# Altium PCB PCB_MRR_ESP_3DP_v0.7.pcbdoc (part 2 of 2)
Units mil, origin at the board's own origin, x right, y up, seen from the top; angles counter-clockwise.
Board outline 5220 x 5030 mil, 2 copper layers (Top Layer, Bottom Layer); 131 components, 154 nets, 480 pads, 88 vias.
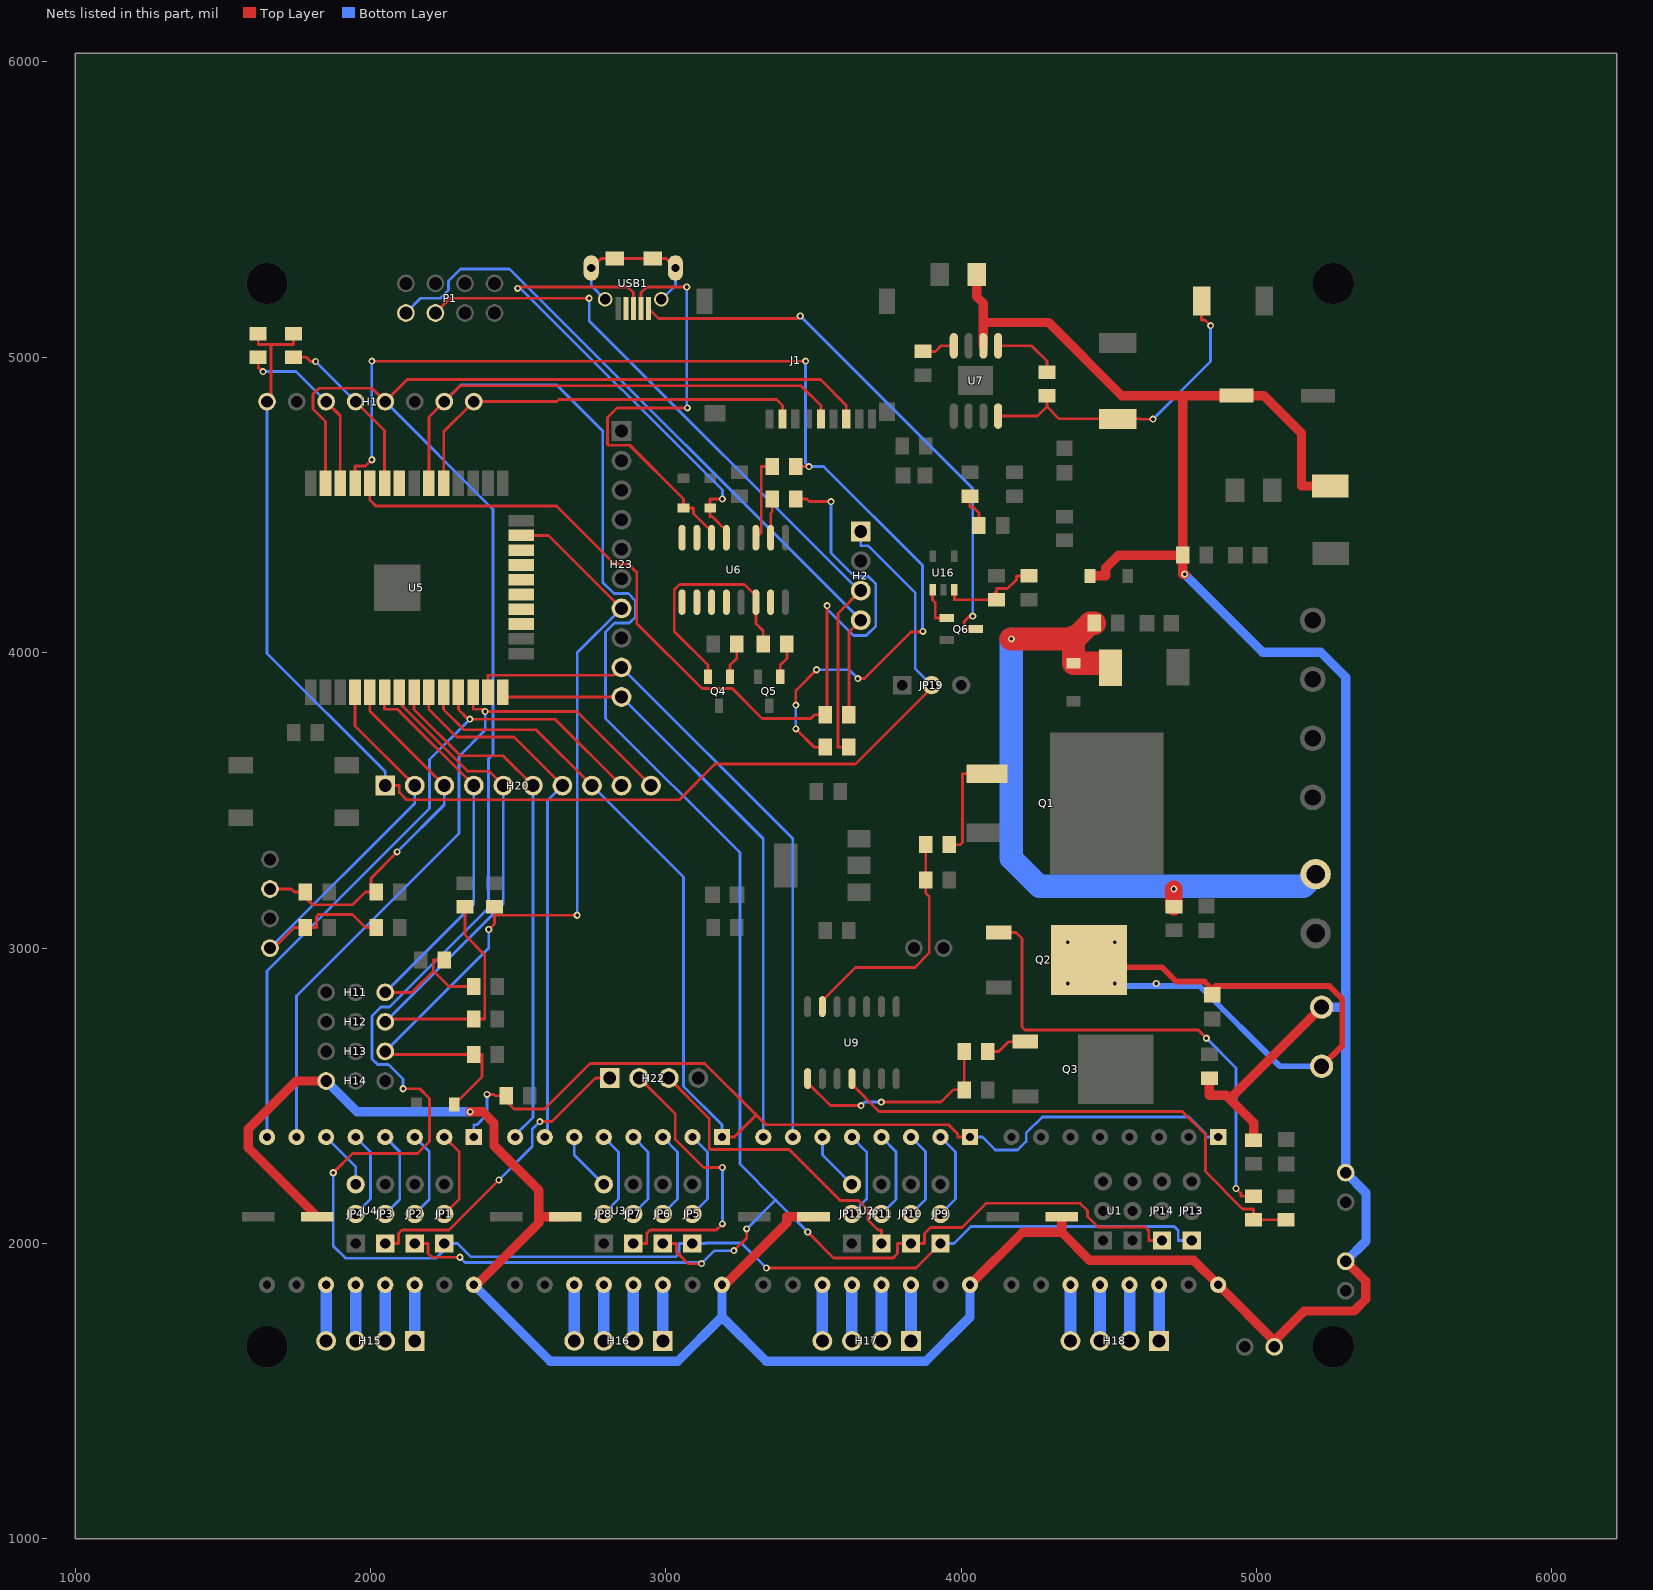
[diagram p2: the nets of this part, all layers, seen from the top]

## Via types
v1: diameter 24.02, hole 12.2, Top Layer to Bottom Layer, 71 vias
v2: diameter 24.4, hole 12, Top Layer to Bottom Layer, 17 vias

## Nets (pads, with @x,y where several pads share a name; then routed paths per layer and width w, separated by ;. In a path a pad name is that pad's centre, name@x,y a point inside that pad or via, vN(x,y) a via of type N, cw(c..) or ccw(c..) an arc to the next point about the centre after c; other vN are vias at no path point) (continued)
MOSI: H1.5 J1.7 JP1.1 JP5.1 JP9.1 JP13.1 U5.37 | length 9016.5
  Top Layer w9.45: U5.37@1848.1,4574.1 1848.1,4782.8 1805.7,4825.2 1805.7,4875.2 1825.5,4895 2005,4895 H1.5@2050,4850 2124.5,4924.5 3523.3,4924.5 3611,4836.8 J1.7@3611,4791 ; v1(1874.2,2239.4) 1939.6,2304.9 2160,2304.9 2200,2344.9 2200,2490.4 2166.8,2523.6 v1(2110.7,2523.6) ; v1(3340.5,1916.9) 3846.9,1916.9 JP9.1@3930,2000
  Bottom Layer w9.45: v1(1874.2,2239.4) 1874.2,1991.2 1915.1,1950.2 2222.9,1950.2 JP1.1@2272.6,2000 ; H1.5@2050,4850 2414.8,4485.2 2414.8,3655.4 2400,3640.6 2400,3135.3 2064.7,2800 2035.2,2800 2005.7,2770.5 2005.7,2624.8 2024.8,2605.7 2061.4,2605.7 2110.7,2556.5 v1(2110.7,2523.6) ; JP1.1@2250,2000 JP1.1@2272.6,2000 ; v1(3340.5,1916.9) 3255.5,2001.9 3137.1,2001.9 3135.3,2000 JP5.1@3090,2000 3044.7,2000 3044.7,1966 3033.4,1954.7 2340.5,1954.7 2295.3,2000 JP1.1@2272.6,2000 ; JP9.1@3930,2000 3975.3,2000 4032.6,2057.3 4721.4,2057.3 4734.7,2043.9 4734.7,2010 JP13.1@4780,2010
MOTOR_EN_PIN: H20.8 R26.1 U1.1 U2.1 U3.1 U4.1 U5.10 | length 5157.6
  Top Layer w9.45: U5.10@2247.8,3865.8 2247.8,3808.2 2317.1,3739 2561,3739 H20.8@2750,3550 ; v1(2394.7,2504.6) 2418.4,2504.6 2422.9,2500 R26.1@2441.5,2500 ; R26.1@2460,2500 R26.1@2441.5,2500 ; U3.1@3190,2360 3231.8,2360 3306.1,2434.3 ; U2.1@4030,2360 3988.2,2360 3988.2,2370.4 3956.9,2401.8 3338.7,2401.8 3306.1,2434.3 ; R26.1@2441.5,2500 2486.2,2455.2 2589.5,2455.2 2743.1,2608.8 3131.6,2608.8 3306.1,2434.3
  Bottom Layer w9.45: U4.1@2350,2360 2350,2401.8 2360.4,2401.8 2394.7,2436 v1(2394.7,2504.6) ; H20.8@2750,3550 3060,3240 3060,2531.8 3190,2401.8 U3.1@3190,2360 ; U2.1@4030,2360 4071.8,2360 4115.6,2316.2 4190.7,2316.2 4220,2345.5 4220,2373.6 4274.7,2428.3 4770.3,2428.3 4828.2,2370.4 4828.2,2360 U1.1@4870,2360
Q2_1: Q2.1 R7.2 | length 1652.7
  Top Layer w9.45: Q2.1@4127.4,3053 4185,3053 4205.5,3032.4 4205.5,2733.2 4216.3,2722.4 4802.4,2722.4 v1(4830,2694.7) ; v1(4930.4,2186.1) 4946.8,2169.7 4946.8,2159.9 R7.2@4990,2159.9
  Bottom Layer w9.45: v1(4830,2694.7) 4930.4,2594.3 v1(4930.4,2186.1)
Q2_4: LED6.2 P7.1 Q2.4 | length 2134
  Top Layer w19.68: Q2.4@4432.7,2960 4432.7,2942.3 4440,2935 4679.6,2935 4727.9,2886.7 4823.3,2886.7 LED6.2@4850.1,2859.9 ; LED6.2@4850.1,2842 LED6.2@4850.1,2859.9 ; P7.1@5220,2600 5289.7,2669.7 5289.7,2827.9 5245.9,2871.6 4861.7,2871.6 LED6.2@4850.1,2859.9
  Bottom Layer w19.68: 4437.5,2950 4515.8,2871.7 4806.7,2871.7 5078.3,2600 P7.1@5220,2600
  other v2: 4360,2880 4520,2880 4660,2880 4360,3020 4520,3020
Q4_1: Q4.1 R19.2 | length 120.2
  Top Layer w9.45: Q4.1@3217.4,3919.2 3217.4,3958.1 3240,3980.7 R19.2@3240,4030
Q5_1: Q5.1 R18.2 | length 120.2
  Top Layer w9.45: Q5.1@3387.4,3919.2 3387.4,3958.1 3410,3980.7 R18.2@3410,4030
R5_2: Q1.1 R5.2 | length 363.3
  Top Layer w9.45: R5.2@3960,3350 3997.1,3350 4004.3,3357.3 4004.3,3590 Q1.1@4087.5,3590
R9_2: Q3.1 R9.2 | length 141.2
  Top Layer w9.45: R9.2@4089.95,2650 4127.1,2650 4127.1,2650.2 4159.8,2683 Q3.1@4217.4,2683
R31_1: C9.1 R31.1 | length 118.5
  Top Layer w9.45: R31.1@4030,4530 4030,4492.9 4040.3,4492.9 4060,4473.2 C9.1@4060,4430
RTS: Q4.2 R18.1 U6.14 | length 814
  Top Layer w9.45: Q4.2@3142.6,3919.2 3142.6,3958.1 3028.3,4072.4 3028.3,4212.9 3046.2,4230.9 3266.6,4230.9 3305,4192.4 U6.14@3305,4171 3305,4098.2 3330,4073.2 R18.1@3330,4030
RX: R17.2 R28.1 U5.34 | length 3251.7
  Top Layer w9.45: U5.34@1998,4574 1998,4516.4 2018.1,4496.4 2630.5,4496.4 2826.9,4300 2873.6,4300 2901.6,4272 2901.6,4099.3 3122.2,3878.7 3224.9,3878.7 3326,3777.6 3490.5,3777.6 3502.9,3790 R28.1@3521.5,3790 ; R17.2@3440,4520 3477.1,4520 3485.7,4511.3 v1(3559.1,4511.3) ; R28.1@3540,3790 R28.1@3521.5,3790 ; v1(3546,4159.1) 3546,3814.5 R28.1@3521.5,3790
  Bottom Layer w9.45: v1(3546,4159.1) 3546,4147.7 3635.7,4057.9 3678.5,4057.9 3711,4090.4 3711,4231.9 3685.2,4257.7 3639.2,4257.7 3559.1,4337.8 v1(3559.1,4511.3)
RXD: H2.4 P1.8 R28.2 | length 2448.7
  Top Layer w9.45: R28.2@3620,3790 3620,4070 H2.4@3660,4110
  Bottom Layer w9.45: P1.8@2120,5150 2170,5200 2236.9,5200 2264.3,5227.4 2264.3,5257.9 2305.3,5299 2471,5299 H2.4@3660,4110
S$12: 
S$15: 
S$17: 
S$18: 
S$20: 
S$26: 
S$28: 
S$39: 
S$41: 
S$43: 
S$91: 
S$93: 
S$150: 
S$152: 
S$180: 
S$236: 
S$240: 
SCK: H1.7 J1.5 JP2.1 JP6.1 JP10.1 JP14.1 U5.30 | length 8421.4
  Top Layer w9.45: JP2.1@2150,2000 2195.3,2000 2195.3,1966 2208,1953.3 v1(2302.6,1953.3) ; U5.30@2197.9,4573.9 2197.9,4797.9 H1.7@2250,4850 2303.8,4903.8 3457.9,4903.8 3525,4836.8 J1.5@3525,4791 ; JP6.1@2990,2000 3035.3,2000 3035.3,1971.8 3075.6,1931.5 v1(3120.7,1931.5) ; v1(3230.5,1975.6) 3273.8,2018.9 v1(3273.8,2049.4) ; v1(3480.5,2038.9) 3568.3,1951.1 3769.8,1951.1 3784.7,1966.1 3784.7,2000 JP10.1@3830,2000 3852.6,2000 3875.3,2000 3875.3,2033.5 3895.9,2054.2 4002.5,2054.2 4084,2135.8 4402.4,2135.8 4427.2,2111 4427.2,2091.7 4463.6,2055.3 4623.4,2055.3 4634.7,2043.9 4634.7,2010 JP14.1@4680,2010
  Bottom Layer w9.45: H1.7@2250,4850 2306.2,4906.2 2630.6,4906.2 2786.5,4750.3 2786.5,4238.2 2824.7,4200 2873.1,4200 2897.7,4175.4 2897.7,4121.3 2876.4,4100 2826.9,4100 2796.3,4069.4 2796.3,3777.8 3250.8,3323.3 3250.8,2268.6 3371.9,2147.5 ; v1(2302.6,1953.3) 2320.1,1935.7 3116.5,1935.7 v1(3120.7,1931.5) 3164.9,1975.6 v1(3230.5,1975.6) ; v1(3273.8,2049.4) 3371.9,2147.5 ; v1(3480.5,2038.9) 3371.9,2147.5
SCL: H1.3 R20.1 U5.36 | length 609.7
  Top Layer w9.45: R20.1@1620,5000 1620,4962.9 1625,4962.9 v1(1636.4,4951.6) ; H1.3@1850,4850 1898,4802 U5.36@1898,4574
  Bottom Layer w9.45: v1(1636.4,4951.6) 1748.4,4951.6 H1.3@1850,4850
SDA: H1.4 R21.1 U5.33 | length 588.7
  Top Layer w9.45: R21.1@1740,5000 1783.2,5000 1797.6,4985.6 v1(1814.4,4985.6) ; H1.4@1950,4850 2048,4752 U5.33@2048,4574
  Bottom Layer w9.45: v1(1814.4,4985.6) H1.4@1950,4850
SS: H1.8 J1.2 U5.29 | length 1420.2
  Top Layer w9.45: U5.29@2247.9,4573.9 2247.9,4747.9 H1.8@2350,4850 2631.1,4850 2637.8,4856.7 3375,4856.7 3395,4836.8 J1.2@3395,4791
TEMP_BED_PIN: C6.1 H10.1 H20.3 R12.1 U5.5 | length 1301.7
  Top Layer w9.45: H10.1@1660,3200 1732.9,3200 1742.9,3190 C6.1@1761.5,3190 ; C6.1@1780,3190 C6.1@1761.5,3190 ; U5.5@1997.9,3865.9 1997.9,3802.1 H20.3@2250,3550 ; R12.1@2020,3190 R12.1@2001.5,3190 ; v1(2090.4,3325.5) 2001.5,3236.5 R12.1@2001.5,3190 ; C6.1@1761.5,3190 1804.6,3146.8 1939.8,3146.8 1982.9,3190 R12.1@2001.5,3190
  Bottom Layer w9.45: v1(2090.4,3325.5) 2250,3485.1 H20.3@2250,3550
TEMP_E0_PIN: C5.1 H9.1 H20.2 R11.1 U5.4 | length 1599.1
  Top Layer w9.45: H9.1@1660,3000 1672.9,3000 1742.9,3070 C5.1@1780,3070 1817.1,3070 1817.1,3107.1 1823.2,3113.2 1939.8,3113.2 1982.9,3070 R11.1@2020,3070 ; U5.4@1947.9,3865.9 1947.9,3752.1 H20.2@2150,3550
  Bottom Layer w9.45: H9.1@1660,3000 2150,3490 H20.2@2150,3550
TO_E0: R7.1 R8.1 U9.11 | length 1774.3
  Top Layer w9.45: U9.11@3630,2558 3630,2538.8 3722.1,2446.8 4748.2,2446.8 4826.7,2368.2 4826.7,2243.2 4952.9,2117.1 4990,2117.1 4990,2079.9 R8.1@5100,2079.9
TO_FAN_E0: R9.1 R10.1 U9.8 | length 727.9
  Top Layer w9.45: U9.8@3480,2558 3480,2544.2 3557.5,2466.7 v1(3661.1,2466.7) ; v1(3729.2,2478.6) 3931.4,2478.6 3972.8,2520 R10.1@4009.95,2520 R9.1@4009.95,2650
  Bottom Layer w9.45: v1(3661.1,2466.7) 3673.1,2478.6 v1(3729.2,2478.6)
TO_HEAT_BED: R5.1 R6.1 U9.6 | length 820.5
  Top Layer w9.45: U9.6@3530,2802 3530,2822.7 3641.8,2934.5 3843.1,2934.5 3891.6,2983.1 3891.6,3175.2 3880,3186.8 R6.1@3880,3230 R5.1@3880,3350
TX: R16.2 R27.1 U5.35 | length 3871.8
  Top Layer w9.45: U5.35@1948,4574 1948,4631.6 1983.2,4631.6 v1(2004.8,4653.2) ; v1(2004.8,4986.9) v1(3473.3,4986.9) ; R16.2@3440,4630 v1(3484.9,4630) ; v1(3440.2,3742.2) 3502.4,3680 R27.1@3540,3680 ; v1(3440.2,3822.2) 3440.2,3872.2 v1(3510.2,3942.2) ; v1(3650.2,3912.2) 3672.2,3912.2 3830,4070 3868,4070 v1(3870.2,4072.2)
  Bottom Layer w9.45: v1(2004.8,4653.2) v1(2004.8,4986.9) ; v1(3440.2,3742.2) v1(3440.2,3822.2) ; v1(3473.3,4986.9) 3473.3,4641.6 v1(3484.9,4630) 3534.4,4630 3868.5,4295.9 3868.5,4073.9 v1(3870.2,4072.2) ; v1(3510.2,3942.2) 3620.2,3942.2 v1(3650.2,3912.2)
TXD: H2.3 P1.6 R27.2 | length 2514.5
  Top Layer w9.45: P1.6@2220,5150 2270,5200 v1(2740.6,5200) ; R27.2@3620,3680 3582.9,3680 3582.9,4132.9 H2.3@3660,4210
  Bottom Layer w9.45: v1(2740.6,5200) 2740.6,5123.7 3654.2,4210 H2.3@3660,4210
U1_11: H18.4 U1.11 | length 190
  Bottom Layer w39.37: H18.4@4370,1670 U1.11@4370,1860
U1_12: H18.3 U1.12 | length 190
  Bottom Layer w39.37: H18.3@4470,1670 U1.12@4470,1860
U1_13: H18.2 U1.13 | length 190
  Bottom Layer w39.37: H18.2@4570,1670 U1.13@4570,1860
U1_14: H18.1 U1.14 | length 190
  Bottom Layer w39.37: H18.1@4670,1670 U1.14@4670,1860
U2_11: H17.4 U2.11 | length 190
  Bottom Layer w39.37: H17.4@3530,1670 U2.11@3530,1860
U2_12: H17.3 U2.12 | length 190
  Bottom Layer w39.37: H17.3@3630,1670 U2.12@3630,1860
U2_13: H17.2 U2.13 | length 190
  Bottom Layer w39.37: H17.2@3730,1670 U2.13@3730,1860
U2_14: H17.1 U2.14 | length 190
  Bottom Layer w39.37: H17.1@3830,1670 U2.14@3830,1860
U3_11: H16.4 U3.11 | length 190
  Bottom Layer w39.37: H16.4@2690,1670 U3.11@2690,1860
U3_12: H16.3 U3.12 | length 190
  Bottom Layer w39.37: H16.3@2790,1670 U3.12@2790,1860
U3_13: H16.2 U3.13 | length 190
  Bottom Layer w39.37: H16.2@2890,1670 U3.13@2890,1860
U3_14: H16.1 U3.14 | length 190
  Bottom Layer w39.37: H16.1@2990,1670 U3.14@2990,1860
U4_11: H15.4 U4.11 | length 190
  Bottom Layer w39.37: H15.4@1850,1670 U4.11@1850,1860
U4_12: H15.3 U4.12 | length 190
  Bottom Layer w39.37: H15.3@1950,1670 U4.12@1950,1860
U4_13: H15.2 U4.13 | length 190
  Bottom Layer w39.37: H15.2@2050,1670 U4.13@2050,1860
U4_14: H15.1 U4.14 | length 190
  Bottom Layer w39.37: H15.1@2150,1670 U4.14@2150,1860
U5_17: U5.17
U5_18: U5.18
U5_19: U5.19
U5_20: U5.20
U5_21: U5.21
U5_22: U5.22
U5_32: U5.32
U6_2: R17.1 U6.2 | length 133.1
  Top Layer w9.45: U6.2@3355,4389 3355,4471.8 3360,4476.8 R17.1@3360,4520
U6_3: R16.1 U6.3 | length 285.5
  Top Layer w9.45: U6.3@3305,4389 3322.9,4406.9 3322.9,4630 R16.1@3360,4630
U6_5: D5.1 U6.5 USB1.3 | length 1662.8
  Top Layer w9.45: v1(2498.2,5233.5) 2503,5238.3 2870.9,5238.3 2890.5,5218.8 USB1.3@2890.5,5165.1 ; v1(3191.7,4520.1) 3150,4520.1 D5.1@3150,4490.05 3150,4460 3157.5,4460 3205,4412.5 U6.5@3205,4389
  Bottom Layer w9.45: v1(2498.2,5233.5) 2508.7,5233.5 3191.7,4550.5 v1(3191.7,4520.1)
U6_6: D6.1 U6.6 USB1.2 | length 1526.7
  Top Layer w9.45: USB1.2@2916,5165.1 2916,5218.8 2935.4,5238.1 v1(3070.9,5238.1) ; v1(3072.9,4828.5) 2835,4828.5 2802.2,4795.7 2802.2,4705 2805,4702.2 2877.8,4702.2 3060,4520.1 D6.1@3060,4490.05 3094,4490 3094,4471.1 3155,4410 U6.6@3155,4389
  Bottom Layer w9.45: v1(3070.9,5238.1) 3070.9,4830.5 v1(3072.9,4828.5)
U6_7: U6.7
U6_8: U6.8
U6_9: U6.9
U6_10: U6.10
U6_11: U6.11
U6_12: U6.12
U6_15: U6.15
U7_1: C15.1 U7.1 | length 223.6
  Top Layer w9.45: U7.1@4125,5039 4238.1,5039 4290,4987.1 C15.1@4290,4950
U7_4: R32.1 U7.4 | length 112.9
  Top Layer w9.45: R32.1@3870,5020 3913.2,5020 3932.2,5039 U7.4@3975,5039
U7_8: C15.2 D4.2 L1.1 U7.8 | length 1091.9
  Top Layer w9.45: U7.8@4125,4801 4258.1,4801 4290,4832.9 ; C15.2@4290,4870 4290,4832.9 ; v1(4649.4,4790.4) 4608.5,4790.4 4607.3,4791.6 D4.2@4530,4791.6 4331.3,4791.6 4290,4832.9 ; L1.1@4813.7,5190 4813.7,5126.5 4825.2,5126.5 v1(4844.2,5107.4)
  Bottom Layer w9.45: v1(4649.4,4790.4) 4844.2,4985.3 v1(4844.2,5107.4)
U16_1: Q6.1 U16.1 | length 138.1
  Top Layer w9.45: U16.1@3903.1,4213 3903.1,4179 3911.9,4170.1 3911.9,4117.4 Q6.1@3950.8,4117.4
U16_3: R23.1 R30.1 U16.3 | length 361.9
  Top Layer w9.45: U16.3@3977.1,4213 3977.1,4179 4090,4179 4120,4209 ; R23.1@4120,4179.99 4120,4208.3 4120,4209 ; R30.1@4230.01,4260 4186.8,4260 4186.8,4246.8 4157.1,4217.1 4120,4217.1 4120,4209
USB1_0: USB1.0 | length 564.6
  Top Layer w9.45: USB1.0@2747.5,5302.31 2748.8,5302.3 2781.4,5334.9 USB1.0@2827.2,5334.9 2873,5334.9 2873.6,5334.2 USB1.0@2956.3,5334.25 2979.2,5334.2 3002.1,5334.2 3002.1,5332.7 USB1.0@3032.5,5302.31
  Bottom Layer w9.45: USB1.0@2747.5,5302.31 2747.5,5242.8 USB1.0@2794.3,5196.01 ; USB1.0@2984.9,5196.01 3032.5,5243.6 USB1.0@3032.5,5302.31
USB1_4: USB1.4
VBED: CN2.2 D2.2 F1.2 R3.1 R14.1 | length 2409.1
  Top Layer w59.05: R3.1@4720,3140 v2(4720,3200)
  Top Layer w78.74: v1(4169.8,4046.5) 4380,4046.5 ; R14.1@4450,4100 4436.3,4100 4389.1,4052.8 4380,4052.8 4380,4046.5 ; F1.2@4505.7,3949.5 4491.2,3964 D2.2@4380,3964 4380,4046.5
  Bottom Layer w78.74: v1(4169.8,4046.5) 4169.8,3304.2 4264.8,3209.1 5159.1,3209.1 CN2.2@5200,3250
VIN: C1.1 C2.1 C3.1 C4.1 C8.1 C14.1 D1.2 F2.2 H7.1 H8.1 H14.1 H19.1 P7.2 R1.1 R2.1 R13.1 U1.16 U2.16 U3.16 U4.16 U7.2 | length 12891.1
  Top Layer w31.5: C1.1@1820,2090 1586.1,2323.9 1586.1,2387.6 1748.5,2550 H14.1@1850,2550 ; v1(2337.4,2445.4) 2380.5,2445.4 2418.4,2407.4 2418.4,2331.6 2569.4,2180.6 2569.4,2090 ; U4.16@2350,1860 2360.2,1860 2569.4,2069.3 2569.4,2090 ; C2.1@2660,2090 2569.4,2090 ; U3.16@3190,1860 3200.2,1860 3409.4,2069.3 3409.4,2090 C3.1@3500,2090 ; U2.16@4030,1860 4207.9,2037.8 4340,2037.8 ; C8.1@4052.99,5280 4053,5205.2 4075,5183.2 4075,5117.8 ; U7.2@4075,5039 4075,5117.8 ; C4.1@4340,2090 4340,2037.8 ; D1.2@4436,4260 4489.4,4260 4489.4,4286.7 4532.7,4330 R13.1@4750,4330 ; v1(4756.5,4265.6) 4750,4265.6 R13.1@4750,4330 ; R1.1@4840,2560 4840,2501.7 4896.6,2501.7 4909.2,2489.1 ; R2.1@4990.1,2350 4990.1,2408.3 4909.2,2489.1 ; H8.1@5060,1650 H8.1@5060,1670 ; P7.2@5220,2800 4909.2,2489.1 ; F2.2@5249.5,4564.3 5152,4564.3 5152,4742.9 5024.8,4870.2 C14.1@4932.2,4870.2 4862.7,4870.2 4750,4870.2 ; H7.1@5301.5,1939.9 5369.5,1871.9 5369.5,1810.9 5330,1771.3 5161.3,1771.3 H8.1@5060,1670 ; 4075,5117.8 4296,5117.8 4543.5,4870.2 4750,4870.2 ; 4340,2037.8 4434.3,1943.5 4786.5,1943.5 U1.16@4870,1860 H8.1@5060,1670 ; R13.1@4750,4330 4750,4870.2
  Bottom Layer w31.5: H14.1@1850,2550 1954.6,2445.4 v1(2337.4,2445.4) ; U4.16@2350,1860 2609,1601 3040,1601 3190,1751 ; U3.16@3190,1860 3190,1751 ; U2.16@4030,1860 4030,1751 3880,1601 3340,1601 3190,1751 ; v1(4756.5,4265.6) 5020.4,4001.6 5216.8,4001.6 5301.5,3917 5301.5,2800 ; P7.2@5220,2800 5301.5,2800 ; H7.1@5301.5,1939.9 5370.3,2008.6 5370.3,2171.1 H19.1@5301.5,2239.9 5301.5,2800
VOUT: H1.1 H2.1 H20.1 JP19.2 R20.2 R21.2 | length 4541.4
  Top Layer w9.45: R20.2@1620,5080 1620,5042.9 1663.2,5042.9 ; H1.1@1650,4850 1663.2,4863.2 1663.2,5042.9 ; R21.2@1740,5080 1740,5042.9 1663.2,5042.9 ; H20.1@2050,3550 2097.8,3550 2097.8,3526.1 2121.6,3502.2 3046.3,3502.2 3167.1,3623 3642,3623 3900,3881 JP19.2@3900,3890
  Bottom Layer w9.45: H1.1@1650,4850 1650,3997.8 2050,3597.8 H20.1@2050,3550 ; H2.1@3660,4410 3660,4362.2 3683.9,4362.2 3844.7,4201.4 3844.7,3945.3 JP19.2@3900,3890
VUSB: Q6.3 USB1.1 | length 1889.2
  Top Layer w9.45: USB1.1@2941.6,5165.1 2975.3,5131.4 3447,5131.4 v1(3455.2,5139.6) ; v1(4039.1,4123.8) 4028.9,4123.8 4010.3,4105.3 4010.3,4080 Q6.3@4049.2,4080
  Bottom Layer w9.45: v1(3455.2,5139.6) 4039.1,4555.7 v1(4039.1,4123.8)
X_CS: H22.1 JP3.1 | length 1046.6
  Top Layer w9.45: JP3.1@2050,2000 2095.3,2000 2095.3,2033.9 2106.6,2045.3 2265.5,2045.3 v1(2434.9,2214.7) ; v1(2573.6,2412.6) 2614.9,2412.6 2762.2,2560 H22.1@2810,2560
  Bottom Layer w9.45: v1(2434.9,2214.7) 2547.6,2327.3 2547.6,2386.6 v1(2573.6,2412.6)
X_DIR_PIN: H20.9 U4.8 U5.11 | length 2416
  Top Layer w9.45: U5.11@2297.8,3865.8 2297.8,3808.2 2331.3,3774.8 v1(2336.8,3774.8) 2625.2,3774.8 H20.9@2850,3550
  Bottom Layer w9.45: U4.8@1650,2360 1650,2922.2 2200,3472.2 2200,3638 v1(2336.8,3774.8)
X_MIN: C11.1 H11.3 H20.4 R24.1 U5.6 | length 1717.2
  Top Layer w9.45: U5.6@2047.9,3865.9 2047.9,3808.3 2091.7,3808.3 H20.4@2350,3550 ; H11.3@2050,2850 2140,2850 2212.9,2922.9 ; C11.1@2250,2960 2212.9,2960 2212.9,2922.9 ; R24.1@2350,2870 2265.9,2870 2212.9,2922.9
  Bottom Layer w9.45: H11.3@2050,2850 2350,3150 H20.4@2350,3550
X_MS1: JP1.2 U4.2 | length 302.3
  Top Layer w9.45: JP1.2@2250,2100 2301,2150.9 2301,2309 U4.2@2250,2360
X_MS2: JP2.2 U4.3 | length 300.8
  Bottom Layer w9.45: JP2.2@2150,2100 2199.3,2149.3 2199.3,2310.7 U4.3@2150,2360
X_MS3: JP3.2 U4.4 | length 300.9
  Bottom Layer w9.45: JP3.2@2050,2100 2099.4,2149.4 2099.4,2310.6 U4.4@2050,2360
X_RST: JP4.2 U4.5 | length 301.4
  Bottom Layer w9.45: JP4.2@1950,2100 2000,2150 2000,2310 U4.5@1950,2360
X_SLP: JP4.3 U4.6 | length 201.4
  Bottom Layer w9.45: U4.6@1850,2360 1950,2260 JP4.3@1950,2200
X_STEP_PIN: H20.10 U4.7 U5.12 | length 2472.2
  Top Layer w9.45: U5.12@2347.9,3865.9 2347.9,3808.3 2381.2,3808.3 v1(2388.5,3801) 2699,3801 H20.10@2950,3550
  Bottom Layer w9.45: U4.7@1750,2360 1750,2838.3 2300,3388.3 2300,3648.8 2388.5,3737.3 v1(2388.5,3801)
Y_CS: H22.2 JP7.1 | length 997.1
  Top Layer w9.45: JP7.1@2890,2000 2935.3,2000 2935.3,2033.9 2946.6,2045.3 3170.8,2045.3 v1(3191.7,2066.1) ; H22.2@2910,2560 3032.3,2437.7 3032.3,2352.4 3127.6,2257.1 v1(3191.7,2257.1)
  Bottom Layer w9.45: v1(3191.7,2066.1) v1(3191.7,2257.1)
Y_DIR_PIN: H20.6 U3.8 U5.8 | length 1781.6
  Top Layer w9.45: U5.8@2147.8,3865.8 2147.8,3808.2 2305,3651.1 2448.9,3651.1 H20.6@2550,3550
  Bottom Layer w9.45: U3.8@2490,2360 2490,2366.2 2550,2426.2 H20.6@2550,3550
Y_MIN: C12.1 H12.3 H20.5 R25.1 U5.7 | length 2219.3
  Top Layer w9.45: H12.3@2050,2750 2060,2760 2331.5,2760 R25.1@2350,2760 2387.1,2760 2387.1,2976.9 2320,3044 C12.1@2320,3140 ; U5.7@2097.9,3865.9 2097.9,3829 2328,3598.9 2401.1,3598.9 H20.5@2450,3550
  Bottom Layer w9.45: H12.3@2050,2750 2450,3150 H20.5@2450,3550
Y_MS1: JP5.2 U3.2 | length 302.3
  Bottom Layer w9.45: JP5.2@3090,2100 3141,2150.9 3141,2309 U3.2@3090,2360
Y_MS2: JP6.2 U3.3 | length 301.4
  Bottom Layer w9.45: JP6.2@2990,2100 3040,2150 3040,2310 U3.3@2990,2360
Y_MS3: JP7.2 U3.4 | length 301.4
  Bottom Layer w9.45: JP7.2@2890,2100 2940,2150 2940,2310 U3.4@2890,2360
Y_RST: JP8.2 U3.5 | length 301.4
  Bottom Layer w9.45: JP8.2@2790,2100 2840,2150 2840,2310 U3.5@2790,2360
Y_SLP: JP8.3 U3.6 | length 201.4
  Bottom Layer w9.45: U3.6@2690,2360 2690,2300 JP8.3@2790,2200
Y_STEP_PIN: H20.7 U3.7 U5.9 | length 1831.6
  Top Layer w9.45: U5.9@2197.8,3865.8 2197.8,3808.2 2291.6,3714.4 2485.6,3714.4 H20.7@2650,3550
  Bottom Layer w9.45: U3.7@2590,2360 2599.9,2369.8 2599.9,3499.8 H20.7@2650,3550
Z_CS: H22.3 JP11.1 | length 1057.8
  Top Layer w9.45: H22.3@3010,2560 3146.7,2423.3 3146.7,2321 3149.5,2318.2 3417.8,2318.2 3590.7,2145.3 3651.8,2145.3 3684.7,2112.3 3684.7,2079.2 3718.7,2045.3 3730,2045.3 JP11.1@3730,2000
Z_DIR_PIN: H23.10 U2.8 U5.14 | length 2097.5
  Top Layer w9.45: U5.14@2447.9,3865.9 2463.8,3850 H23.10@2850,3850
  Bottom Layer w9.45: H23.10@2850,3850 3330,3370 U2.8@3330,2360
Z_MIN: C13.1 D3.2 H13.3 H23.7 R29.1 U5.23 | length 3006.5
  Top Layer w9.45: H13.3@2050,2650 2060,2640 R29.1@2350,2640 2368.5,2640 2377.8,2640 2377.8,2563.8 D3.2@2284,2470 ; v1(2400.7,3062.8) 2420,3082.1 2420,3111 ; C13.1@2420,3140 2420,3111 ; U5.23@2511,4396.9 2603.1,4396.9 H23.7@2850,4150 ; v1(2700,3111) 2420,3111
  Bottom Layer w9.45: H13.3@2050,2650 2400.7,3000.7 v1(2400.7,3062.8) ; v1(2700,3111) 2700,4000 H23.7@2850,4150
Z_MS1: JP9.2 U2.2 | length 302.3
  Bottom Layer w9.45: JP9.2@3930,2100 3981,2150.9 3981,2309 U2.2@3930,2360
Z_MS2: JP10.2 U2.3 | length 300.8
  Bottom Layer w9.45: JP10.2@3830,2100 3879.3,2149.3 3879.3,2310.7 U2.3@3830,2360
Z_MS3: JP11.2 U2.4 | length 300.9
  Bottom Layer w9.45: JP11.2@3730,2100 3779.4,2149.4 3779.4,2310.6 U2.4@3730,2360
Z_RST: JP12.2 U2.5 | length 301.4
  Bottom Layer w9.45: JP12.2@3630,2100 3680,2150 3680,2310 U2.5@3630,2360
Z_SLP: JP12.3 U2.6 | length 201.4
  Bottom Layer w9.45: U2.6@3530,2360 3530,2300 JP12.3@3630,2200
Z_STEP_PIN: H23.9 U2.7 U5.13 | length 2350.9
  Top Layer w9.45: U5.13@2397.9,3865.9 2397.9,3923.5 2823.5,3923.5 H23.9@2850,3950
  Bottom Layer w9.45: H23.9@2850,3950 3430,3370 U2.7@3430,2360
pads on no net: H3.1 H4.1 H5.1 H6.1 P1.5 P1.7 U5.39 U7.3 U7.9
copper on no net:
  other v2: 1970,4110 2130,4110 2270,4110 1970,4220 2130,4220 2270,4220 1970,4340 2130,4340 2270,4340

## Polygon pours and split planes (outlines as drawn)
GND on Bottom Layer (solid): 5670,4230 5610,5530 3060,5500 3070,5150 2620,5170 2710,4810 2920,4810 2910,3650 3020,3630 3040,3480 1730,3480 1730,2920 2110,2900 2230,2430 2720,2430 2780,2630 3200,2660 3230,2430 4930,2400 4930,1740 5270,1740 5240,2500 5160,2510 5090,2580 5110,3720 4050,3700 4020,3820 3730,3840 3730,4010 3590,4050 3590,4480 3730,4500 3750,4130 3880,3960 4080,3950 4130,3790 5060,3780 5080,4200
GND on Top Layer (solid): 5720,4200 5680,5450 3060,5480 3050,5140 2920,5130 2910,3640 3020,3610 3020,3480 1730,3480 1710,2910 2120,2900 2090,2430 2730,2450 2750,2630 3200,2630 3190,2430 4920,2420 4910,1750 5230,1750 5230,2490 5120,2490 5110,3720 3750,3680 3760,4030 3590,4030 3600,4460 3760,4480 3860,3950 4080,3950 4090,3780 5080,3800 5080,4220

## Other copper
Top Layer:
  region net Q2_4: 4230,3120 4650,3120 4650,2750 4230,2750 4230,2840 4230,3000
  region: 1900,4020 1900,4430 2370,4430 2370,4020
  region net LED5_2: 4300,3730 5030,3730 5030,3210 4840,3200 4810,3250 4760,3250 4300,3250 4300,3280 4260,3330 4260,3680
  region net LED5_2: 4800,3240 4800,3120 4970,3120 4970,3000 5100,3000 5100,3350 5000,3350 5000,3240 4810,3230
  region net Q2_4: 4660,3000 4890,3000 5060,2930 5060,2810 4810,2810 4690,2810 4670,2790 4630,2790 4630,3000
Bottom Layer:
  region net LED5_2: 4300,3280 4260,3330 4260,3680 4300,3730 4690,3730 4740,3730 4930,3730 5030,3730 5030,3280
  region net Q2_4: 4220,3120 4650,3120 4650,2780 4230,2780 4230,2870 4230,3030
  region: 1900,4020 1900,4430 2370,4430 2370,4020
  region net LED7_2: 4210,2640 4700,2640 4700,2460 4210,2460
  region net Q2_4: 4660,3000 4990,3000 4990,2820 4980,2810 4700,2810 4650,2790 4610,2810 4620,3000

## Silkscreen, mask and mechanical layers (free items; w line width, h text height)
Top Overlay:
  text "TF_Card" at 3380,5004.97 h33.46
  text "IO5" at 2369.68,4930 h39.37 r90
  text "5V" at 4397.39,4756.13 h33.46 r86
  text "GND" at 2670,4718.81 h39.37
  text "SS" at 2369.68,4710 h39.37 r90
  text "GND" at 1769.68,4670 h39.37 r90
  text "SCL" at 1869.68,4670 h39.37 r90
  text "SDA" at 1969.68,4670 h39.37 r90
  text "SCK" at 2269.68,4670 h39.37 r90
  text "MOSI" at 2068.18,4650.6 h39.37 r90
  text "MISO" at 2168.18,4650.6 h39.37 r90
  text "Vout" at 1669.68,4649.66 h39.37 r89
  text "IO17" at 2670,4620.31 h39.37
  text "IO16" at 2670,4520.31 h39.37
  text "IO4" at 2690,4420.31 h39.37
  text "Vout" at 3739.66,4390.32 h39.37 r359
  text "IO0" at 2690,4320.31 h39.37
  text "VIN" at 5069.71,4304.97 h33.46 r359
  text "GND" at 3740,4290.31 h39.37
  text "IO2" at 2690,4220.31 h39.37
  text "TX" at 3740,4190.31 h39.37
  text "VBED" at 4630,4154.97 h33.46
  text "IO15" at 2670,4120.31 h39.37
  text "RX" at 3740,4090.32 h39.37
  text "VIN" at 4891.72,4063.48 h59.05 r89
  text "12-24V" at 4945.03,4045.1 h33.46 r90
  text "IO13" at 2670,4020.32 h39.37
  text "5V" at 3766.43,3956.11 h33.46 r356
  text "3.3V" at 3955.8,3956.07 h33.46
  text "IO14" at 2670,3920.32 h39.37
  text "GND" at 4891.73,3859.1 h59.05 r90
  text "IO12" at 2670,3820.32 h39.37
  text "Vout_SEL" at 3770.34,3780.32 h39.37 r1
  text "BOOT" at 1530,3668.82 h39.37
  text "VP" at 2169.64,3641.37 h39.37 r94
  text "VN" at 2269.68,3640 h39.37 r90
  text "IO34" at 2369.68,3640 h39.37 r90
  text "IO35" at 2469.68,3640 h39.37 r90
  text "IO32" at 2569.68,3640 h39.37 r90
  text "IO33" at 2661.18,3640 h39.37 r90
  text "IO25" at 2759.68,3640 h39.37 r90
  text "IO26" at 2869.68,3640 h39.37 r90
  text "IO27" at 2969.68,3640 h39.37 r90
  text "Vout" at 2069.68,3629.66 h39.37 r89
  text "12-24V" at 4946.73,3620 h33.46 r90
  text "VBED" at 4899.53,3610 h59.05 r90
  text "GND" at 4899.53,3430 h59.05 r90
  text "T_BED" at 1537.5,3370 h45 r270
  text "MRR_ESP_3DP" at 2170,3330.63 h78.74
  text "v0.7" at 3050,3330.63 h78.74
  text "BED" at 4819.42,3213.6 h47.24 r90
  text "3V" at 3288.54,3165.03 h33.46 r355
  text "BED+" at 4951.73,3153.8 h59.05 r90
  text "T_E0" at 1537.5,3110 h45 r270
  text "MOS_EN" at 3780,3068.82 h39.37
  text "-" at 4930,3051.23 h59.05 r180
  text "V  G  S" at 1840,2930.32 h39.37
  text "Licensed under CERN OHL v.1.2" at 2790,2900.32 h39.37
  text "E0" at 4799.42,2867.8 h47.24 r90
  text "X_MIN" at 2130,2830.32 h39.37
  text "E0+" at 4981.73,2733.8 h59.05 r90
  text "Y_MIN" at 2130,2730.32 h39.37
  text "Z_MIN" at 2129.66,2630.32 h39.37 r359
  text "-" at 4960,2599.53 h59.05 r180
  text "Z_PROBE" at 2130,2530.32 h39.37
  text "X  Y  Z  E0" at 2770,2426.38 h47.24
  text "PART / FAN" at 5282.69,2319.3 h39.37 r90
  text "RST" at 1910,2273.27 h33.46
  text "MS3" at 2010,2273.27 h33.46
  text "MS2" at 2120,2273.27 h33.46
  text "MS1" at 2230,2273.27 h33.46
  text "RST" at 2750,2273.27 h33.46
  text "MS3" at 2850,2273.27 h33.46
  text "MS2" at 2960,2273.27 h33.46
  text "MS1" at 3070,2273.27 h33.46
  text "RST" at 3580,2273.27 h33.46
  text "MS3" at 3680,2273.27 h33.46
  text "MS2" at 3790,2273.27 h33.46
  text "MS1" at 3900,2273.27 h33.46
  text "RST" at 4430,2273.27 h33.46
  text "MS3" at 4540,2273.27 h33.46
  text "MS2" at 4650,2273.27 h33.46
  text "MS1" at 4760,2273.27 h33.46
  text "+" at 5200.62,2270.78 h59.05 r225
  text "-" at 5201.5,2116.17 h59.05
  text "VMOT" at 2333.27,2030 h33.46 r270
  text "VMOT" at 3173.27,2030 h33.46 r270
  text "VMOT" at 4013.27,2030 h33.46 r270
  text "VMOT" at 4853.27,2030 h33.46 r270
  text "+" at 5200.62,1980.78 h59.05 r225
  text "TMC" at 4430,1913.27 h33.46
  text "SPI" at 4540,1913.27 h33.46
  text "SPI" at 4640,1913.27 h33.46
  text "SPI" at 4740,1913.27 h33.46
  text "TMC" at 1910,1903.27 h33.46
  text "SPI" at 2020,1903.27 h33.46
  text "SPI" at 2120,1903.27 h33.46
  text "SPI" at 2220,1903.27 h33.46
  text "TMC" at 2750,1903.27 h33.46
  text "SPI" at 2860,1903.27 h33.46
  text "SPI" at 2960,1903.27 h33.46
  text "SPI" at 3060,1903.27 h33.46
  text "TMC" at 3590,1903.27 h33.46
  text "SPI" at 3700,1903.27 h33.46
  text "SPI" at 3800,1903.27 h33.46
  text "SPI" at 3900,1903.27 h33.46
  text "-" at 5201.5,1820.37 h59.05
  text "E0 FAN" at 5161.19,1799.9 h39.37 r90
  text "-" at 4959.53,1760 h59.05 r90
  text "CASE / FAN" at 4770,1738.82 h39.37
  text "+" at 5050.88,1739.12 h59.05 r45
  text "X_MOTOR" at 1830.41,1550.58 h47.24 r1
  text "Y_MOTOR" at 2670.41,1546.38 h47.24 r1
  text "Z_MOTOR" at 3520,1546.38 h47.24
  text "E0_MOTOR" at 4360,1536.38 h47.24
